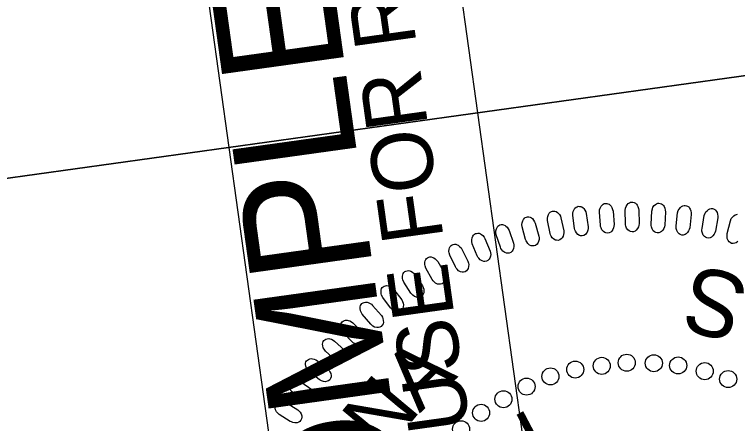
# Model space of a CAD drawing. Extents: x 477288 to 478604, y 497629 to 499448.
# Drawn here: x 477375.5 to 477443.3, y 499167.6 to 499206 of the extents above; entities that cross this region are included whole.
import ezdxf

# ---------------------------------------------------------------- set-up
doc = ezdxf.new("R2010")
doc.units = 0
for name, color, linetype in [('Sheet PE Seal Cell', 7, 'Continuous'), ('Sheet Plan CELL', 7, 'Continuous'), ('Sheet Sticker Incomplete CELL', 7, 'Continuous')]:
    doc.layers.add(name, color=color, linetype=linetype)

msp = doc.modelspace()

# ---------------------------------------------------------------- linework, layer by layer
at = {"layer": 'Sheet PE Seal Cell'}
for points in [[(477427.991, 499185.911), (477427.823, 499187.127), (477427.83, 499187.349), (477427.862, 499187.494), (477427.95, 499187.678), (477428.031, 499187.8), (477428.131, 499187.894), (477428.229, 499187.948), (477428.338, 499187.983), (477428.452, 499187.979), (477428.574, 499187.966), (477428.686, 499187.921), (477428.803, 499187.836), (477428.873, 499187.766), (477428.961, 499187.626), (477429.045, 499187.457), (477429.089, 499187.303), (477429.269, 499186.058), (477429.27, 499185.888), (477429.244, 499185.743), (477429.178, 499185.572), (477429.086, 499185.419), (477429.001, 499185.326), (477428.853, 499185.245), (477428.708, 499185.205), (477428.554, 499185.225), (477428.444, 499185.26), (477428.304, 499185.34), (477428.163, 499185.492), (477428.071, 499185.661), (477428.024, 499185.785)], [(477430.413, 499186.215), (477430.321, 499187.438), (477430.342, 499187.659), (477430.383, 499187.803), (477430.483, 499187.981), (477430.571, 499188.098), (477430.677, 499188.185), (477430.778, 499188.233), (477430.889, 499188.261), (477431.002, 499188.249), (477431.123, 499188.229), (477431.232, 499188.177), (477431.344, 499188.085), (477431.41, 499188.01), (477431.488, 499187.866), (477431.561, 499187.691), (477431.596, 499187.534), (477431.697, 499186.281), (477431.688, 499186.111), (477431.653, 499185.968), (477431.576, 499185.802), (477431.474, 499185.655), (477431.384, 499185.568), (477431.232, 499185.496), (477431.084, 499185.465), (477430.932, 499185.494), (477430.824, 499185.536), (477430.69, 499185.626), (477430.558, 499185.786), (477430.477, 499185.96), (477430.438, 499186.086)], [(477432.753, 499186.372), (477432.739, 499187.599), (477432.773, 499187.819), (477432.823, 499187.959), (477432.933, 499188.131), (477433.029, 499188.242), (477433.141, 499188.322), (477433.244, 499188.364), (477433.357, 499188.385), (477433.469, 499188.366), (477433.589, 499188.337), (477433.694, 499188.279), (477433.8, 499188.181), (477433.861, 499188.102), (477433.93, 499187.953), (477433.992, 499187.774), (477434.016, 499187.615), (477434.039, 499186.359), (477434.019, 499186.188), (477433.976, 499186.048), (477433.888, 499185.888), (477433.778, 499185.747), (477433.682, 499185.666), (477433.525, 499185.604), (477433.376, 499185.583), (477433.226, 499185.621), (477433.121, 499185.669), (477432.992, 499185.767), (477432.871, 499185.935), (477432.801, 499186.114), (477432.77, 499186.243)], [(477435.172, 499186.309), (477435.235, 499187.533), (477435.283, 499187.75), (477435.342, 499187.888), (477435.463, 499188.052), (477435.566, 499188.156), (477435.681, 499188.23), (477435.788, 499188.264), (477435.901, 499188.279), (477436.012, 499188.253), (477436.13, 499188.217), (477436.231, 499188.152), (477436.331, 499188.047), (477436.387, 499187.964), (477436.446, 499187.812), (477436.497, 499187.63), (477436.511, 499187.469), (477436.455, 499186.214), (477436.424, 499186.045), (477436.372, 499185.908), (477436.274, 499185.754), (477436.156, 499185.62), (477436.055, 499185.545), (477435.895, 499185.493), (477435.744, 499185.481), (477435.597, 499185.528), (477435.495, 499185.583), (477435.373, 499185.689), (477435.263, 499185.864), (477435.204, 499186.048), (477435.182, 499186.178)], [(477437.516, 499186.149), (477437.655, 499187.368), (477437.717, 499187.581), (477437.784, 499187.714), (477437.915, 499187.87), (477438.024, 499187.968), (477438.145, 499188.035), (477438.253, 499188.062), (477438.367, 499188.069), (477438.476, 499188.037), (477438.592, 499187.994), (477438.689, 499187.923), (477438.781, 499187.812), (477438.832, 499187.726), (477438.882, 499187.569), (477438.921, 499187.384), (477438.925, 499187.223), (477438.79, 499185.974), (477438.749, 499185.808), (477438.688, 499185.674), (477438.582, 499185.526), (477438.454, 499185.4), (477438.349, 499185.332), (477438.186, 499185.29), (477438.035, 499185.287), (477437.891, 499185.343), (477437.793, 499185.405), (477437.677, 499185.518), (477437.578, 499185.7), (477437.531, 499185.887), (477437.517, 499186.018)], [(477425.704, 499185.442), (477425.459, 499186.645), (477425.453, 499186.867), (477425.475, 499187.014), (477425.551, 499187.203), (477425.625, 499187.329), (477425.719, 499187.43), (477425.813, 499187.489), (477425.919, 499187.532), (477426.033, 499187.535), (477426.156, 499187.529), (477426.271, 499187.492), (477426.393, 499187.415), (477426.468, 499187.348), (477426.564, 499187.215), (477426.658, 499187.051), (477426.712, 499186.9), (477426.97, 499185.669), (477426.981, 499185.499), (477426.965, 499185.353), (477426.909, 499185.179), (477426.827, 499185.02), (477426.748, 499184.922), (477426.606, 499184.832), (477426.463, 499184.783), (477426.309, 499184.792), (477426.196, 499184.82), (477426.052, 499184.893), (477425.901, 499185.035), (477425.799, 499185.197), (477425.744, 499185.318)], [(477439.939, 499185.908), (477440.154, 499187.116), (477440.23, 499187.325), (477440.305, 499187.454), (477440.446, 499187.601), (477440.56, 499187.692), (477440.685, 499187.751), (477440.795, 499187.772), (477440.908, 499187.772), (477441.015, 499187.732), (477441.128, 499187.681), (477441.22, 499187.605), (477441.306, 499187.488), (477441.351, 499187.399), (477441.391, 499187.24), (477441.418, 499187.053), (477441.413, 499186.892), (477441.2, 499185.653), (477441.147, 499185.491), (477441.079, 499185.361), (477440.963, 499185.219), (477440.828, 499185.101), (477440.719, 499185.04), (477440.553, 499185.009), (477440.402, 499185.016), (477440.263, 499185.081), (477440.168, 499185.148), (477440.06, 499185.268), (477439.973, 499185.457), (477439.938, 499185.645), (477439.931, 499185.778)], [(477423.395, 499184.875), (477423.076, 499186.06), (477423.055, 499186.281), (477423.068, 499186.43), (477423.132, 499186.623), (477423.197, 499186.754), (477423.285, 499186.86), (477423.375, 499186.926), (477423.479, 499186.974), (477423.592, 499186.984), (477423.716, 499186.986), (477423.833, 499186.956), (477423.959, 499186.887), (477424.037, 499186.826), (477424.142, 499186.698), (477424.247, 499186.541), (477424.31, 499186.393), (477424.644, 499185.181), (477424.666, 499185.012), (477424.659, 499184.865), (477424.615, 499184.688), (477424.543, 499184.524), (477424.47, 499184.422), (477424.334, 499184.322), (477424.194, 499184.265), (477424.04, 499184.264), (477423.926, 499184.286), (477423.777, 499184.348), (477423.618, 499184.481), (477423.506, 499184.637), (477423.444, 499184.754)], [(477421.034, 499184.145), (477420.641, 499185.306), (477420.606, 499185.526), (477420.61, 499185.675), (477420.662, 499185.872), (477420.719, 499186.007), (477420.8, 499186.119), (477420.886, 499186.19), (477420.986, 499186.245), (477421.098, 499186.262), (477421.222, 499186.271), (477421.339, 499186.249), (477421.47, 499186.188), (477421.553, 499186.132), (477421.665, 499186.011), (477421.779, 499185.86), (477421.851, 499185.717), (477422.261, 499184.528), (477422.294, 499184.361), (477422.297, 499184.214), (477422.263, 499184.034), (477422.201, 499183.866), (477422.135, 499183.76), (477422.005, 499183.652), (477421.87, 499183.586), (477421.716, 499183.575), (477421.601, 499183.589), (477421.448, 499183.643), (477421.281, 499183.765), (477421.159, 499183.914), (477421.09, 499184.027)], [(477418.871, 499183.329), (477418.406, 499184.464), (477418.358, 499184.681), (477418.352, 499184.83), (477418.392, 499185.03), (477418.44, 499185.168), (477418.514, 499185.284), (477418.595, 499185.361), (477418.692, 499185.422), (477418.803, 499185.447), (477418.925, 499185.464), (477419.044, 499185.449), (477419.179, 499185.396), (477419.265, 499185.345), (477419.384, 499185.232), (477419.508, 499185.088), (477419.589, 499184.949), (477420.072, 499183.79), (477420.116, 499183.624), (477420.127, 499183.478), (477420.105, 499183.296), (477420.055, 499183.125), (477419.995, 499183.014), (477419.872, 499182.899), (477419.741, 499182.824), (477419.588, 499182.804), (477419.472, 499182.81), (477419.317, 499182.854), (477419.142, 499182.966), (477419.012, 499183.107), (477418.935, 499183.215)], [(477416.822, 499182.292), (477416.286, 499183.396), (477416.224, 499183.609), (477416.209, 499183.758), (477416.237, 499183.959), (477416.276, 499184.1), (477416.342, 499184.221), (477416.418, 499184.303), (477416.511, 499184.369), (477416.62, 499184.401), (477416.741, 499184.426), (477416.861, 499184.418), (477416.999, 499184.374), (477417.088, 499184.329), (477417.214, 499184.223), (477417.346, 499184.088), (477417.436, 499183.954), (477417.992, 499182.827), (477418.045, 499182.665), (477418.065, 499182.519), (477418.055, 499182.337), (477418.015, 499182.162), (477417.962, 499182.048), (477417.848, 499181.925), (477417.722, 499181.842), (477417.569, 499181.813), (477417.454, 499181.812), (477417.296, 499181.846), (477417.115, 499181.946), (477416.975, 499182.078), (477416.892, 499182.182)], [(477414.65, 499181.107), (477414.046, 499182.175), (477413.971, 499182.384), (477413.947, 499182.531), (477413.961, 499182.734), (477413.992, 499182.878), (477414.05, 499183.002), (477414.122, 499183.088), (477414.21, 499183.161), (477414.317, 499183.198), (477414.436, 499183.232), (477414.556, 499183.231), (477414.697, 499183.196), (477414.788, 499183.156), (477414.92, 499183.059), (477415.061, 499182.932), (477415.158, 499182.804), (477415.784, 499181.714), (477415.848, 499181.556), (477415.878, 499181.412), (477415.878, 499181.229), (477415.85, 499181.053), (477415.804, 499180.935), (477415.697, 499180.805), (477415.576, 499180.715), (477415.427, 499180.676), (477415.311, 499180.668), (477415.151, 499180.691), (477414.964, 499180.781), (477414.817, 499180.904), (477414.727, 499181.002)], [(477412.645, 499179.839), (477411.975, 499180.867), (477411.886, 499181.071), (477411.853, 499181.216), (477411.855, 499181.42), (477411.877, 499181.565), (477411.927, 499181.693), (477411.993, 499181.783), (477412.076, 499181.862), (477412.181, 499181.906), (477412.297, 499181.946), (477412.417, 499181.953), (477412.56, 499181.927), (477412.653, 499181.893), (477412.792, 499181.804), (477412.939, 499181.686), (477413.045, 499181.565), (477413.738, 499180.516), (477413.811, 499180.362), (477413.85, 499180.22), (477413.862, 499180.038), (477413.845, 499179.86), (477413.807, 499179.74), (477413.708, 499179.604), (477413.594, 499179.505), (477413.447, 499179.457), (477413.332, 499179.442), (477413.171, 499179.456), (477412.978, 499179.533), (477412.823, 499179.646), (477412.728, 499179.739)], [(477410.734, 499178.455), (477410.001, 499179.439), (477409.9, 499179.637), (477409.858, 499179.78), (477409.846, 499179.983), (477409.859, 499180.129), (477409.902, 499180.26), (477409.962, 499180.355), (477410.039, 499180.438), (477410.141, 499180.489), (477410.255, 499180.536), (477410.374, 499180.551), (477410.518, 499180.534), (477410.614, 499180.505), (477410.757, 499180.425), (477410.912, 499180.317), (477411.026, 499180.203), (477411.783, 499179.2), (477411.866, 499179.05), (477411.914, 499178.911), (477411.937, 499178.73), (477411.931, 499178.552), (477411.901, 499178.429), (477411.81, 499178.287), (477411.702, 499178.182), (477411.559, 499178.125), (477411.445, 499178.102), (477411.283, 499178.106), (477411.086, 499178.171), (477410.925, 499178.274), (477410.823, 499178.361)], [(477408.878, 499176.924), (477408.084, 499177.859), (477407.971, 499178.051), (477407.92, 499178.191), (477407.896, 499178.393), (477407.899, 499178.54), (477407.933, 499178.673), (477407.987, 499178.771), (477408.06, 499178.859), (477408.158, 499178.916), (477408.269, 499178.971), (477408.387, 499178.993), (477408.532, 499178.984), (477408.629, 499178.962), (477408.777, 499178.891), (477408.939, 499178.793), (477409.059, 499178.686), (477409.877, 499177.733), (477409.97, 499177.589), (477410.026, 499177.453), (477410.061, 499177.274), (477410.066, 499177.094), (477410.043, 499176.971), (477409.962, 499176.824), (477409.861, 499176.712), (477409.721, 499176.646), (477409.609, 499176.616), (477409.447, 499176.61), (477409.247, 499176.661), (477409.079, 499176.755), (477408.973, 499176.835)], [(477407.143, 499175.268), (477406.293, 499176.152), (477406.168, 499176.336), (477406.108, 499176.473), (477406.071, 499176.673), (477406.066, 499176.819), (477406.091, 499176.954), (477406.139, 499177.056), (477406.206, 499177.148), (477406.301, 499177.212), (477406.407, 499177.273), (477406.524, 499177.303), (477406.668, 499177.303), (477406.767, 499177.287), (477406.92, 499177.226), (477407.087, 499177.138), (477407.214, 499177.039), (477408.09, 499176.138), (477408.191, 499176.001), (477408.256, 499175.869), (477408.302, 499175.692), (477408.318, 499175.513), (477408.304, 499175.388), (477408.232, 499175.237), (477408.138, 499175.118), (477408.003, 499175.044), (477407.893, 499175.007), (477407.732, 499174.99), (477407.528, 499175.03), (477407.355, 499175.112), (477407.244, 499175.186)], [(477405.54, 499173.571), (477404.635, 499174.399), (477404.499, 499174.576), (477404.431, 499174.708), (477404.382, 499174.905), (477404.366, 499175.051), (477404.383, 499175.188), (477404.425, 499175.292), (477404.485, 499175.388), (477404.576, 499175.457), (477404.679, 499175.525), (477404.794, 499175.562), (477404.938, 499175.572), (477405.037, 499175.562), (477405.193, 499175.51), (477405.365, 499175.433), (477405.498, 499175.342), (477406.43, 499174.499), (477406.54, 499174.368), (477406.613, 499174.24), (477406.669, 499174.066), (477406.697, 499173.889), (477406.69, 499173.763), (477406.629, 499173.607), (477406.542, 499173.484), (477406.411, 499173.401), (477406.304, 499173.357), (477406.145, 499173.331), (477405.939, 499173.357), (477405.761, 499173.429), (477405.645, 499173.494)], [(477404.032, 499171.734), (477403.077, 499172.504), (477402.93, 499172.671), (477402.854, 499172.799), (477402.793, 499172.993), (477402.768, 499173.137), (477402.776, 499173.274), (477402.811, 499173.381), (477402.866, 499173.481), (477402.952, 499173.556), (477403.051, 499173.63), (477403.163, 499173.674), (477403.306, 499173.693), (477403.406, 499173.689), (477403.564, 499173.647), (477403.741, 499173.582), (477403.88, 499173.499), (477404.862, 499172.715), (477404.98, 499172.591), (477405.061, 499172.469), (477405.129, 499172.299), (477405.167, 499172.124), (477405.168, 499171.998), (477405.116, 499171.838), (477405.038, 499171.709), (477404.913, 499171.618), (477404.809, 499171.568), (477404.651, 499171.532), (477404.444, 499171.545), (477404.262, 499171.606), (477404.142, 499171.664)], [(477402.595, 499169.772), (477401.594, 499170.481), (477401.436, 499170.638), (477401.352, 499170.762), (477401.279, 499170.951), (477401.245, 499171.094), (477401.245, 499171.231), (477401.273, 499171.34), (477401.322, 499171.443), (477401.403, 499171.523), (477401.496, 499171.603), (477401.605, 499171.654), (477401.747, 499171.682), (477401.848, 499171.685), (477402.008, 499171.653), (477402.189, 499171.598), (477402.332, 499171.525), (477403.362, 499170.804), (477403.487, 499170.688), (477403.575, 499170.571), (477403.654, 499170.405), (477403.703, 499170.234), (477403.712, 499170.108), (477403.67, 499169.945), (477403.6, 499169.811), (477403.481, 499169.713), (477403.38, 499169.656), (477403.226, 499169.61), (477403.018, 499169.61), (477402.833, 499169.659), (477402.71, 499169.71)], [(477401.34, 499167.809), (477400.296, 499168.453), (477400.129, 499168.6), (477400.038, 499168.718), (477399.952, 499168.903), (477399.91, 499169.043), (477399.901, 499169.18), (477399.922, 499169.29), (477399.964, 499169.397), (477400.039, 499169.481), (477400.128, 499169.567), (477400.234, 499169.625), (477400.374, 499169.661), (477400.473, 499169.671), (477400.636, 499169.649), (477400.82, 499169.606), (477400.968, 499169.541), (477402.041, 499168.887), (477402.173, 499168.779), (477402.269, 499168.667), (477402.357, 499168.507), (477402.417, 499168.338), (477402.434, 499168.214), (477402.403, 499168.049), (477402.34, 499167.911), (477402.228, 499167.805), (477402.131, 499167.742), (477401.979, 499167.687), (477401.773, 499167.674), (477401.584, 499167.711), (477401.458, 499167.754)]]:
    msp.add_lwpolyline(points, close=True, dxfattribs=at)
msp.add_lwpolyline([(477443.284, 499184.677), (477443.143, 499184.568), (477443.029, 499184.513), (477442.862, 499184.492), (477442.713, 499184.508), (477442.577, 499184.582), (477442.487, 499184.656), (477442.387, 499184.782), (477442.311, 499184.976), (477442.288, 499185.167), (477442.29, 499185.299), (477442.306, 499185.428), (477442.596, 499186.62), (477442.685, 499186.824), (477442.768, 499186.948), (477442.918, 499187.086), (477443.038, 499187.17), (477443.166, 499187.221), (477443.277, 499187.234)], dxfattribs=at)
for centre in [(477430.54, 499173.017), (477432.885, 499173.313), (477435.426, 499173.264), (477437.707, 499173.058), (477428.054, 499172.672), (477440.195, 499172.519), (477425.73, 499172.028), (477442.389, 499171.779), (477423.49, 499171.073), (477421.322, 499169.888), (477419.228, 499168.615), (477417.351, 499167.068)]:
    msp.add_circle(centre, 0.801, dxfattribs=at)
at = {"layer": 'Sheet Plan CELL'}
msp.add_line((477363.175, 499188.999), (477474.563, 499204.512), dxfattribs=at)
for points in [[(477363.175, 499188.999), (477349.381, 499288.03), (477460.818, 499303.551), (477474.614, 499204.507)], [(477376.966, 499089.904), (477363.175, 499188.999), (477474.614, 499204.507), (477488.378, 499105.421)]]:
    msp.add_lwpolyline(points, close=True, dxfattribs=at)
at = {"layer": 'Sheet Sticker Incomplete CELL'}
msp.add_lwpolyline([(477429.019, 499123.954), (477405.744, 499120.714), (477385.482, 499266.311), (477408.757, 499269.55)], close=True, dxfattribs=at)

# ---------------------------------------------------------------- texts
at = {"layer": 'Sheet PE Seal Cell'}
for s, height, rotation, p in [('S', 6.236, 165.25216, (477444.61, 499181.158)), ('A', 5.669, 43.5955, (477413.46, 499168.532)), ('N', 5.669, 50.08486, (477410.173, 499164.722)), ('L', 5.669, 27.75354, (477424.645, 499163.13))]:
    msp.add_text(s, height=height, rotation=rotation, dxfattribs=at).set_placement(p)
at = {"layer": 'Sheet Plan CELL'}
msp.add_text('ROADWAY DESIGN', height=5.0001, rotation=97.92268, dxfattribs=at).set_placement((477381.525, 499110.1))
at = {"layer": 'Sheet Sticker Incomplete CELL'}
for s, height, p in [('INCOMPLETE PLANS', 11.52, (477416.197, 499131.205)), ('DO NOT USE FOR R/W ACQUISITION', 5.76, (477422.633, 499135.382))]:
    msp.add_text(s, height=height, rotation=97.92268, dxfattribs=at).set_placement(p)

doc.saveas('drawing.dxf')
